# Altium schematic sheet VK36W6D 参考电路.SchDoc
size A4
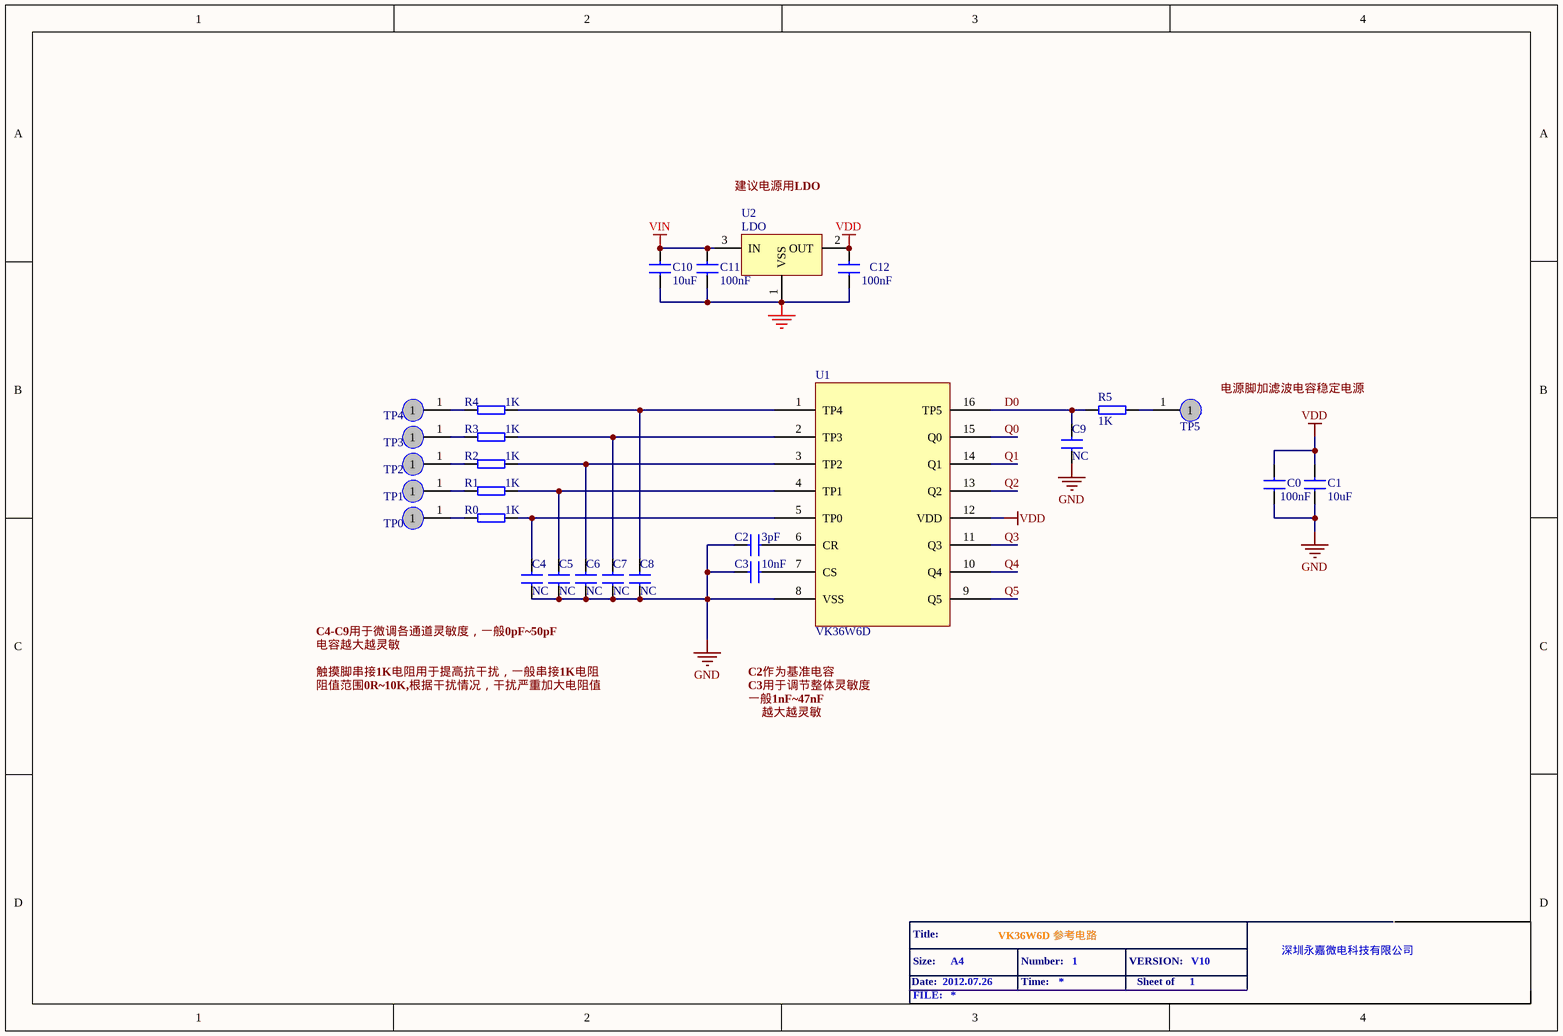
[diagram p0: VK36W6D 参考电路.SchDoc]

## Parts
C0  100nF  [0603-C]
C1  10uF  [0603-C]
C2  value 3pF  [0603-C]  (hidden comment: 10uF)
C3  value 10nF  [0603-C]  (hidden comment: 10uF)
C4  value NC  [0603-C]  (hidden comment: 10uF)
C5  value NC  [0603-C]  (hidden comment: 10uF)
C6  value NC  [0603-C]  (hidden comment: 10uF)
C7  value NC  [0603-C]  (hidden comment: 10uF)
C8  value NC  [0603-C]  (hidden comment: 10uF)
C9  value NC  [0603-C]  (hidden comment: 10uF)
C10  10uF  [0805-C]
C11  100nF  [0805-C]
C12  100nF  [0805-C]
R0  1K  [0603-R]
R1  1K  [0603-R]
R2  1K  [0603-R]
R3  1K  [0603-R]
R4  1K  [0603-R]
R5  1K  [0603-R]
TP0  TPAD  [TP-PAD0]  (value not drawn)
TP1  TPAD  [TP-PAD0]  (value not drawn)
TP2  TPAD  [TP-PAD0]  (value not drawn)
TP3  TPAD  [TP-PAD0]  (value not drawn)
TP4  TPAD  [TP-PAD0]  (value not drawn)
TP5  TPAD  [TP-PAD0]  (value not drawn)
U1  VK36W6D
U2  LDO  [SOT-23]

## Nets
GND: C0.2 C1.2 C2.2 C3.2 C4.1 C5.1 C6.1 C7.1 C8.1 C9.1 C10.2 C11.2 C12.2 U1.8(VSS) U2.1(VSS)
VDD: C0.1 C1.1 C12.1 U1.12(VDD) U2.2(OUT)
VIN: C10.1 C11.1 U2.3(IN)
D0: C9.2 R5.1 U1.16(TP5)
Q0: U1.15(Q0)
Q1: U1.14(Q1)
Q2: U1.13(Q2)
Q3: U1.11(Q3)
Q4: U1.10(Q4)
Q5: U1.9(Q5)
NetC2_1: C2.1 U1.6(CR)
NetC3_1: C3.1 U1.7(CS)
NetC4_2: C4.2 R0.1 U1.5(TP0)
NetC5_2: C5.2 R1.1 U1.4(TP1)
NetC6_2: C6.2 R2.1 U1.3(TP2)
NetC7_2: C7.2 R3.1 U1.2(TP3)
NetC8_2: C8.2 R4.2 U1.1(TP4)
NetR0_2: R0.2 TP0.1
NetR1_2: R1.2 TP1.1
NetR2_2: R2.2 TP2.1
NetR3_2: R3.2 TP3.1
NetR4_1: R4.1 TP4.1
NetR5_2: R5.2 TP5.1

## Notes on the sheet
- 建议电源用LDO
- (near TP5) 电源脚加滤波电容稳定电源
- C4-C9用于微调各通道灵敏度，一般0pF~50pF
- 电容越大越灵敏
- 触摸脚串接1K电阻用于提高抗干扰，一般串接1K电阻
- 阻值范围0R
  0K,根据干扰情况，干扰严重加大电阻值
- C3用于调节整体灵敏度
- 一般1nF~47nF
- C2作为基准电容
- 越大越灵敏
- Date:
- Title:
- Size:
- 2012.07.26
- A4
- VK36W6D 参考电路
- Number:
- Time:
- 1
- VERSION:
- Sheet of
- V10
- 深圳永嘉微电科技有限公司
- FILE:

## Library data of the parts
C0-C12 = CAP: Capacitor
R0-R5 = RES: Resistor
TP0-TP5 = TPAD: TESTING
U2 = V6206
